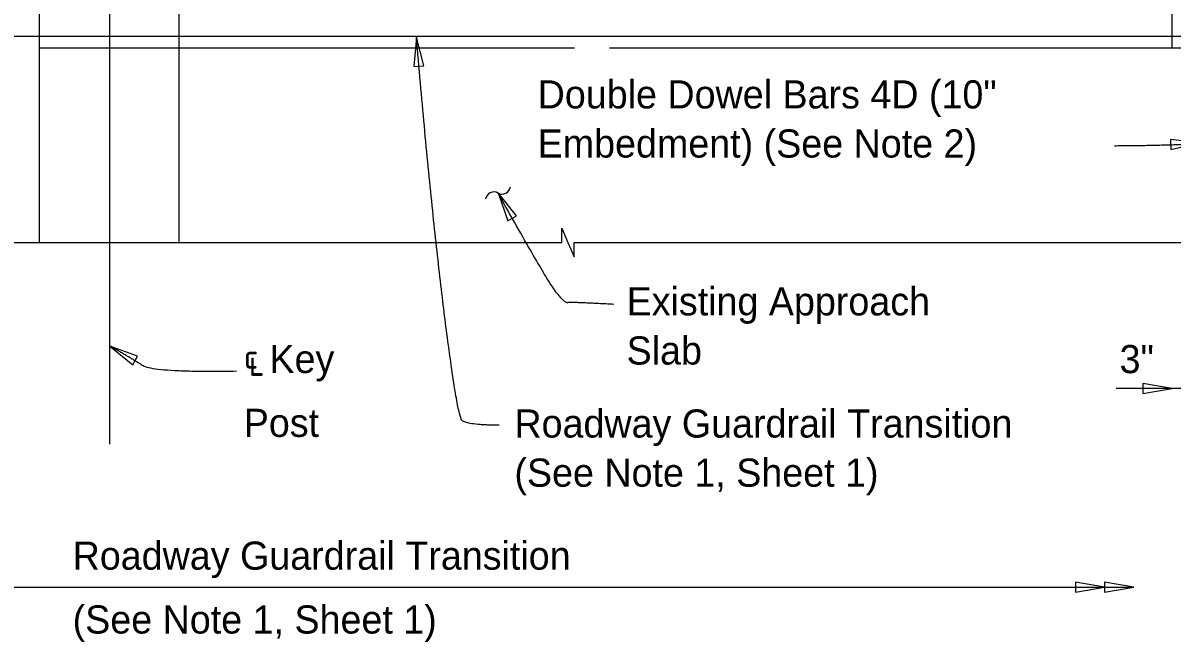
# Model space of a CAD drawing. Extents: x 21526.6 to 21598.7, y 56118.1 to 56155.9.
# Drawn here: x 21554.18 to 21562.41, y 56142.39 to 56146.83 of the extents above; entities that cross this region are included whole.
import ezdxf

# ---------------------------------------------------------------- set-up
doc = ezdxf.new("R2010")
doc.units = 0
for name, color, linetype in [('AdhocPoint_dp', 7, 'Continuous'), ('Border', 7, 'Continuous'), ('PlotBorder_dp', 7, 'Continuous'), ('SheetBorder_dp', 7, 'Continuous'), ('SubStrConc', 7, 'Continuous')]:
    doc.layers.add(name, color=color, linetype=linetype)

msp = doc.modelspace()

# ---------------------------------------------------------------- linework, layer by layer
at = {"layer": 'AdhocPoint_dp'}
for p, q in [((21554.3018, 56145.2536), (21554.3018, 56149.7195)), ((21555.3018, 56145.2536), (21555.3018, 56148.546)), ((21554.3018, 56146.6482), (21558.1329, 56146.6482)), ((21558.3839, 56146.6482), (21565.8764, 56146.6482))]:
    msp.add_line(p, q, dxfattribs=at)
at = {"layer": 'PlotBorder_dp'}
for p, q in [((21554.8018, 56147.4803), (21554.8018, 56143.8094)), ((21565.892, 56144.2072), (21562.0129, 56144.2072))]:
    msp.add_line(p, q, dxfattribs=at)
for points in [[(21557.0004, 56146.7236), (21556.9831, 56146.5131), (21557.0534, 56146.5192)], [(21562.6097, 56145.9668), (21562.3998, 56145.9907), (21562.4037, 56145.9202)], [(21557.5857, 56145.608), (21557.6562, 56145.4089), (21557.7179, 56145.4432)], [(21554.8059, 56144.5108), (21554.9698, 56144.3776), (21555.0045, 56144.439)], [(21562.4118, 56144.2072), (21562.2036, 56144.2425), (21562.2036, 56144.1719)], [(21561.9289, 56142.7836), (21561.7207, 56142.8189), (21561.7207, 56142.7483)], [(21562.1372, 56142.7836), (21561.9289, 56142.8189), (21561.9289, 56142.7483)]]:
    msp.add_lwpolyline(points, close=True, dxfattribs=at)
for points in [[(21553.5912, 56145.2536), (21558.0411, 56145.2536), (21558.0411, 56145.3569), (21558.0861, 56145.2536), (21558.1311, 56145.1503), (21558.1311, 56145.2536), (21560.8244, 56145.2536)], [(21560.8244, 56145.2536), (21563.2763, 56145.2536), (21563.2763, 56145.3569), (21563.3213, 56145.2536), (21563.3663, 56145.1503), (21563.3663, 56145.2536), (21566.0596, 56145.2536)], [(21546.0419, 56142.7836), (21550.1141, 56142.7836), (21550.1141, 56142.8869), (21550.1591, 56142.7836), (21550.2041, 56142.6803), (21550.2041, 56142.7836), (21562.1372, 56142.7836)]]:
    msp.add_lwpolyline(points, dxfattribs=at)
for centre, start, end in [((21557.6145, 56145.6594), 240.3192, 352.04642), ((21557.5555, 56145.5558), 60.3192, 172.04642)]:
    msp.add_arc(centre, 0.0596, start, end, dxfattribs=at)
for points in [[(21557.5924, 56143.9442), (21557.3666, 56143.9442), (21557.2913, 56144.0095), (21557.1007, 56145.5597), (21557.0004, 56146.7236)], [(21561.9997, 56145.9466), (21562.4721, 56145.9497), (21562.9797, 56145.9902), (21564.3467, 56146.1616), (21565.0264, 56146.2754)], [(21558.4139, 56144.8097), (21558.0978, 56144.8272), (21558.0663, 56144.8161), (21557.932, 56144.9858), (21557.5857, 56145.608)], [(21555.7124, 56144.3301), (21555.117, 56144.3201), (21554.9598, 56144.4238), (21554.8059, 56144.5108)]]:
    msp.add_open_spline(points, degree=2, dxfattribs=at)
at = {"layer": 'SheetBorder_dp'}
msp.add_line((21552.8484, 56146.7315), (21566.2337, 56146.7315), dxfattribs=at)
at = {"layer": 'SubStrConc'}
for q in [(21562.4118, 56148.0232), (21565.4118, 56146.6482)]:
    msp.add_line((21562.4118, 56146.6482), q, dxfattribs=at)

# ---------------------------------------------------------------- texts
at = {"layer": 'Border'}
for s, p in [('℄ Key', (21555.7643, 56144.3179)), ('3"', (21562.0364, 56144.317)), ('Post', (21555.7643, 56143.8603))]:
    msp.add_text(s, height=0.2016, dxfattribs=at).set_placement(p)
at = {"layer": 'PlotBorder_dp'}
for s, p in [('Double Dowel Bars 4D (10" ', (21557.8691, 56146.2135)), ('Embedment) (See Note 2)', (21557.8691, 56145.8615)), ('Existing Approach ', (21558.5059, 56144.7307)), ('Slab', (21558.5059, 56144.3787)), ('Roadway Guardrail Transition', (21557.7026, 56143.8555)), ('(See Note 1, Sheet 1)', (21557.7026, 56143.5035)), ('Roadway Guardrail Transition', (21554.539, 56142.909)), ('(See Note 1, Sheet 1)', (21554.539, 56142.4514))]:
    msp.add_text(s, height=0.2016, dxfattribs=at).set_placement(p)

doc.saveas('drawing.dxf')
